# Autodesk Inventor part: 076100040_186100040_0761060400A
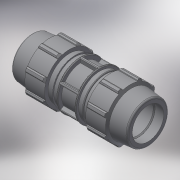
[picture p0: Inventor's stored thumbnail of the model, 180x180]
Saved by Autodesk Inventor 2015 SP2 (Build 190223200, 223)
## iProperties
Created: 2017-02
Part Number: 076100040_186100040_0761060400A
Material: Generic
Description: PLASSON REPAIR COUPLER 40
Document SubType Name: Modeling
Designer: KIM
Mass: 551.487 g
Surface Area: 933.11 cm^2
Volume: 551.487 cm^3
Density: 1 g/cm^3
Appearance: Default
Author: KIM
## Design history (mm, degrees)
derived "07610.ipt"
feature "Solid1::07610.ipt"
tag "TaggingFeature1"
body "Solid1"
other parameters: "d1" = 215, "d4" = 17.91667, "d5" = 30.71429, "d7" = 82, "d8" = 61.5, "d9" = 30.71429, "d11" = 3.48571, "d12" = 65.6, "d13" = 120 deg, "d15" = 10 deg, "d16" = 73.8, "d18" = 2, "d19" = 35 deg, "d20" = 17.5 deg, "d21" = 76.26, "d23" = 0, "d25" = 360 deg, "d27" = 1.64, "d33" = 0.8, "d34" = 4.1, "d36" = 0, "d37" = 0.8, "d38" = 0.8, "d40" = 360 deg, "d42" = 38.7, "d43" = 2.46, "d46" = 1.2, "d50" = 8.08571, "d51" = 65.6, "E_" = 82, "H_" = 215, "l_" = 148, "d49" = 19.65714
